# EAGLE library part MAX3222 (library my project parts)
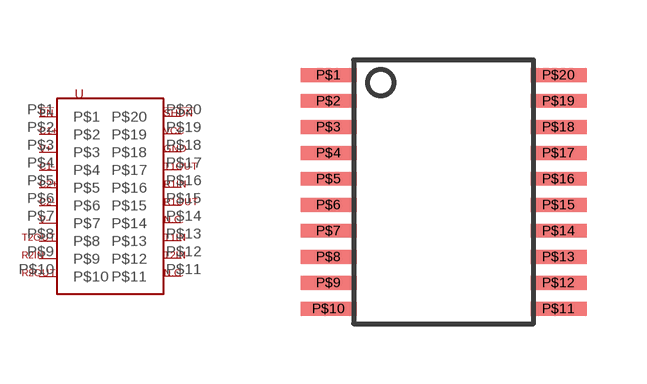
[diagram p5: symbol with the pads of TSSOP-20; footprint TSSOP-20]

Designator prefix -

## MAX3222  [TSSOP-20]
P$1  P$1
P$2  P$2
P$3  P$3
P$4  P$4
P$5  P$5
P$6  P$6
P$7  P$7
P$8  P$8
P$9  P$9
P$10  P$10
P$11  P$11  nc
P$12  P$12
P$13  P$13
P$14  P$14  nc
P$15  P$15
P$16  P$16
P$17  P$17
P$18  P$18
P$19  P$19
P$20  P$20

## Footprint TSSOP-20 (pad centres in mm)
smd 1.4 x 0.35: P$1 -2.875,2.925; P$2 -2.875,2.275; P$3 -2.875,1.625; P$4 -2.875,0.975; P$5 -2.875,0.325; P$6 -2.875,-0.325; P$7 -2.875,-0.975; P$8 -2.875,-1.625; P$9 -2.875,-2.275; P$10 -2.875,-2.925; P$11 2.875,-2.925; P$12 2.875,-2.275; P$13 2.875,-1.625; P$14 2.875,-0.975; P$15 2.875,-0.325; P$16 2.875,0.325; P$17 2.875,0.975; P$18 2.875,1.625; P$19 2.875,2.275; P$20 2.875,2.925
